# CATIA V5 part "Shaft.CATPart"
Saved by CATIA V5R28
Part number: Shaft
Bounding box of the stored display mesh (mm): x -14 to 14, y 0 to 150, z -14 to 14
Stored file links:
  C:\Users\Parisa\Desktop\tarah sanat\Oldham Coupling\Shaft.CATPart
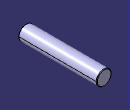
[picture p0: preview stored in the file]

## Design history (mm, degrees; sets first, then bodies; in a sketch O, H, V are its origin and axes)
Body1 (main body)
  Sketch1 on zx-plane, origin (0, 0, 0), H (-1, 0, 0), V (0, 0, 1)
    circle A1 centre (0, 0) radius 14
    radius A1 = 14
  Pad1: profile Sketch1, direction (0, 1, 0), length 150
  Chamfer1: length 1, angle 45, on edge [face of Pad1 from Sketch1.A1 | end face of Pad1]; edge [start face of Pad1 | face of Pad1 from Sketch1.A1]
